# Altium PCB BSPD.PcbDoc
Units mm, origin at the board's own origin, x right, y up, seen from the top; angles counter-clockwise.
Board outline 53 x 50 mm, 2 copper layers (Top Layer, Bottom Layer), stack 1.57 mm thick; 78 components, 28 nets, 171 pads, 73 vias.
Unrouted connection lines stored in the file: 1.
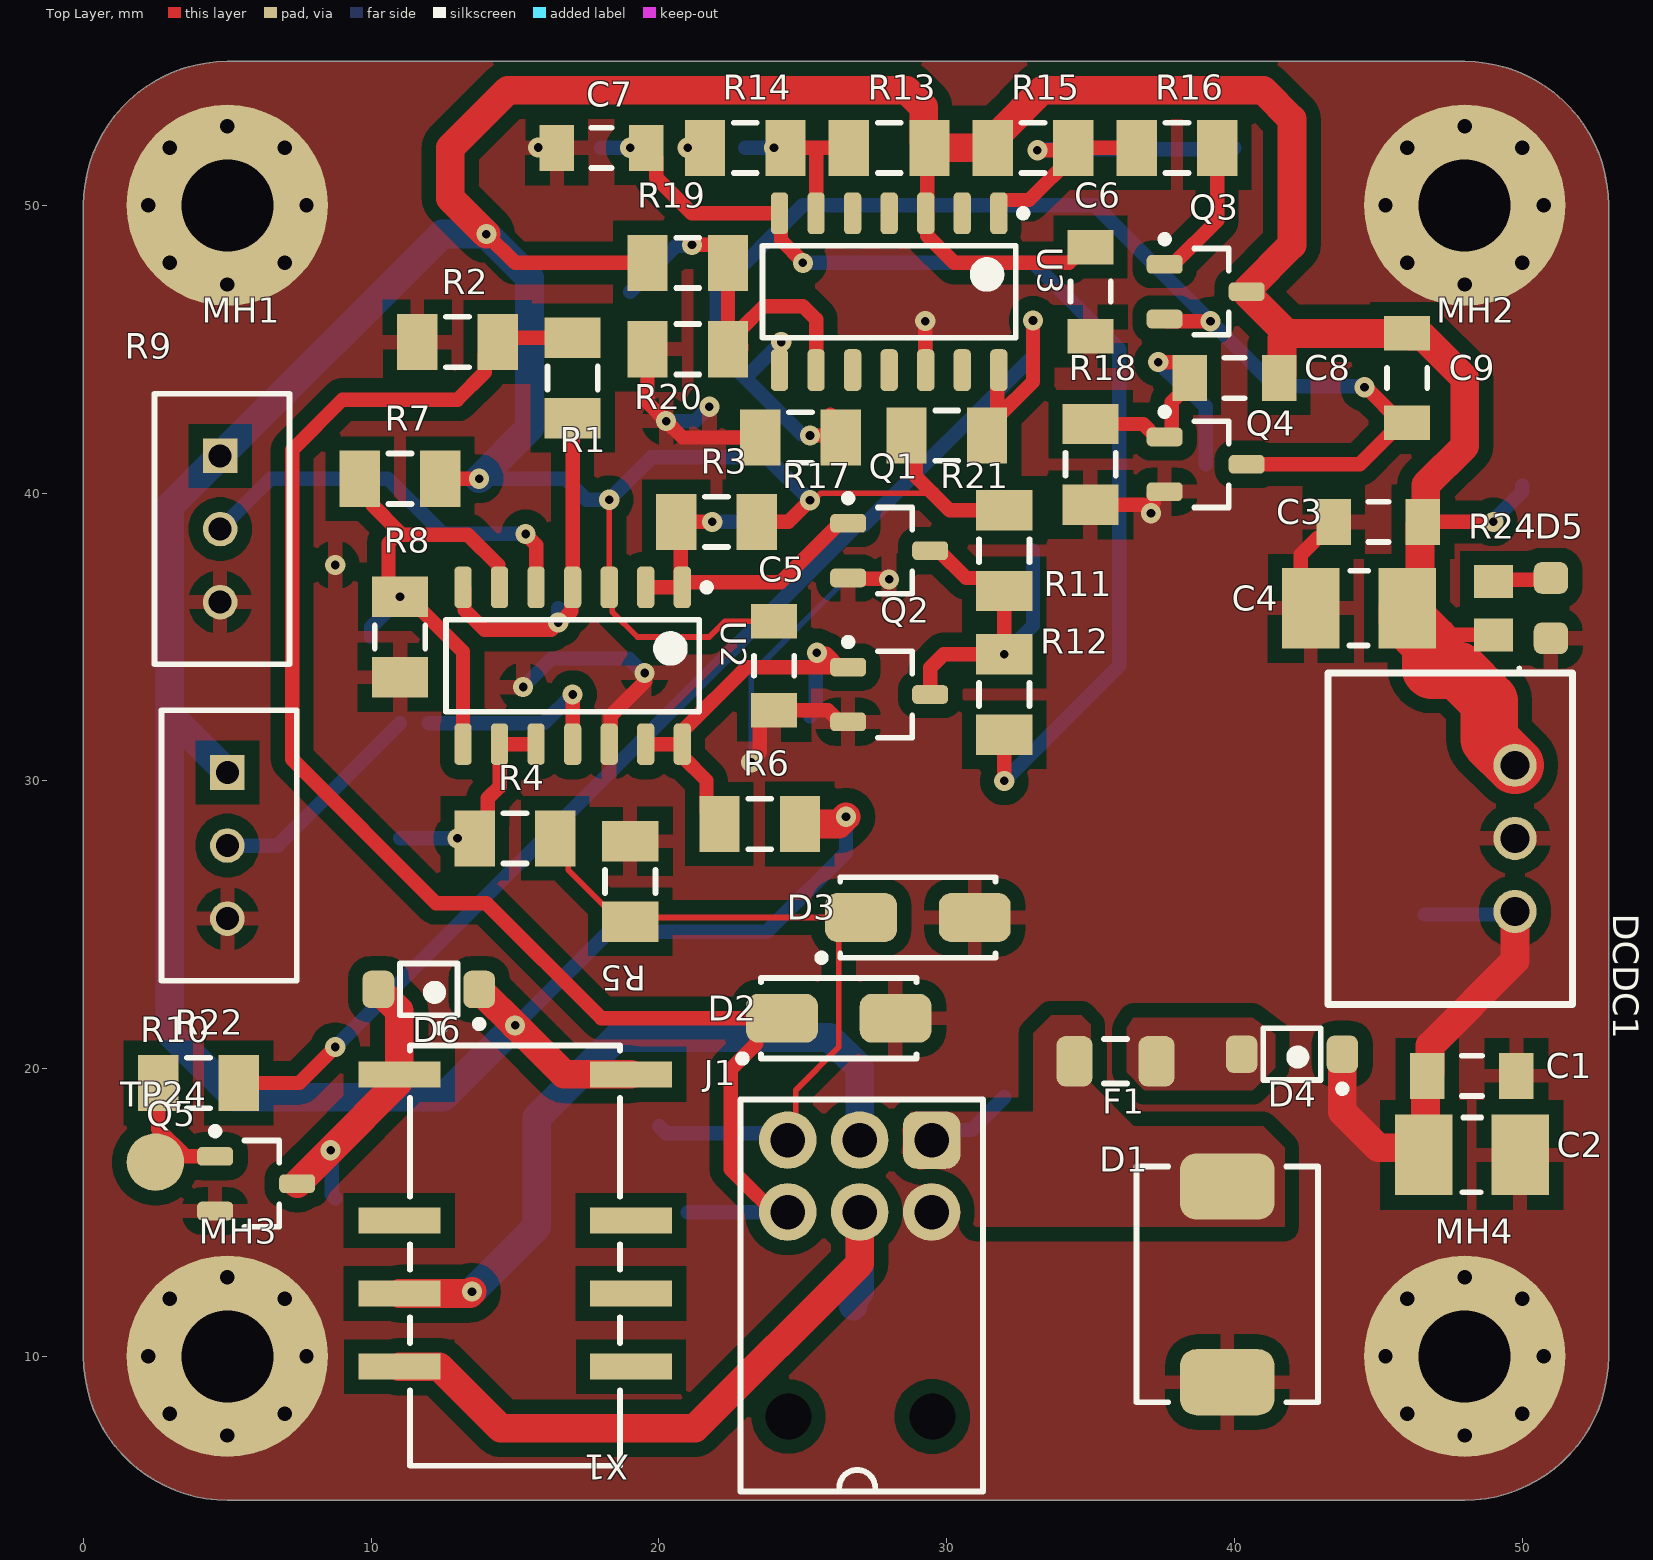
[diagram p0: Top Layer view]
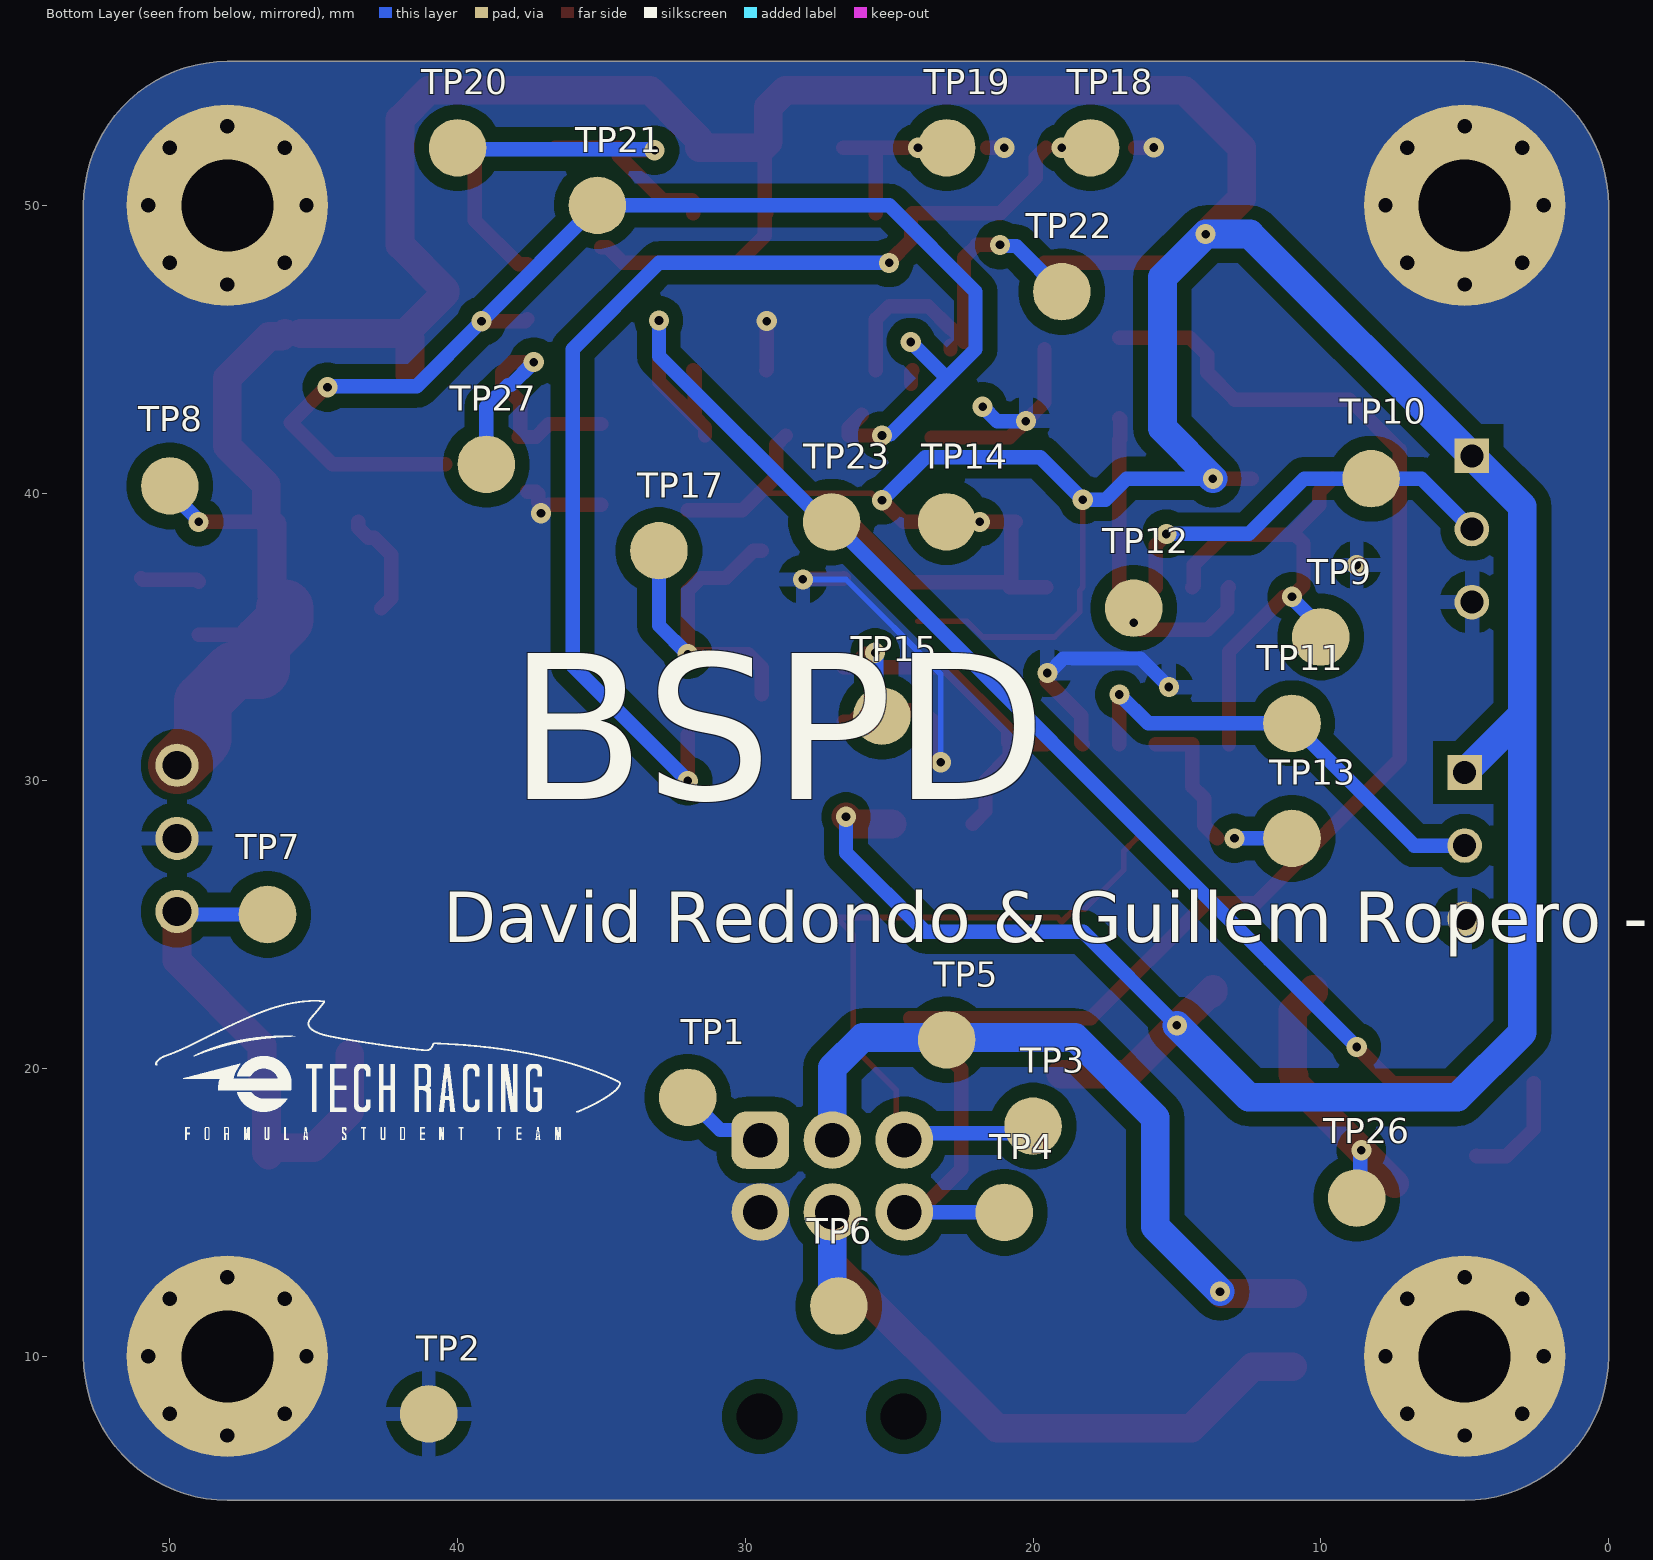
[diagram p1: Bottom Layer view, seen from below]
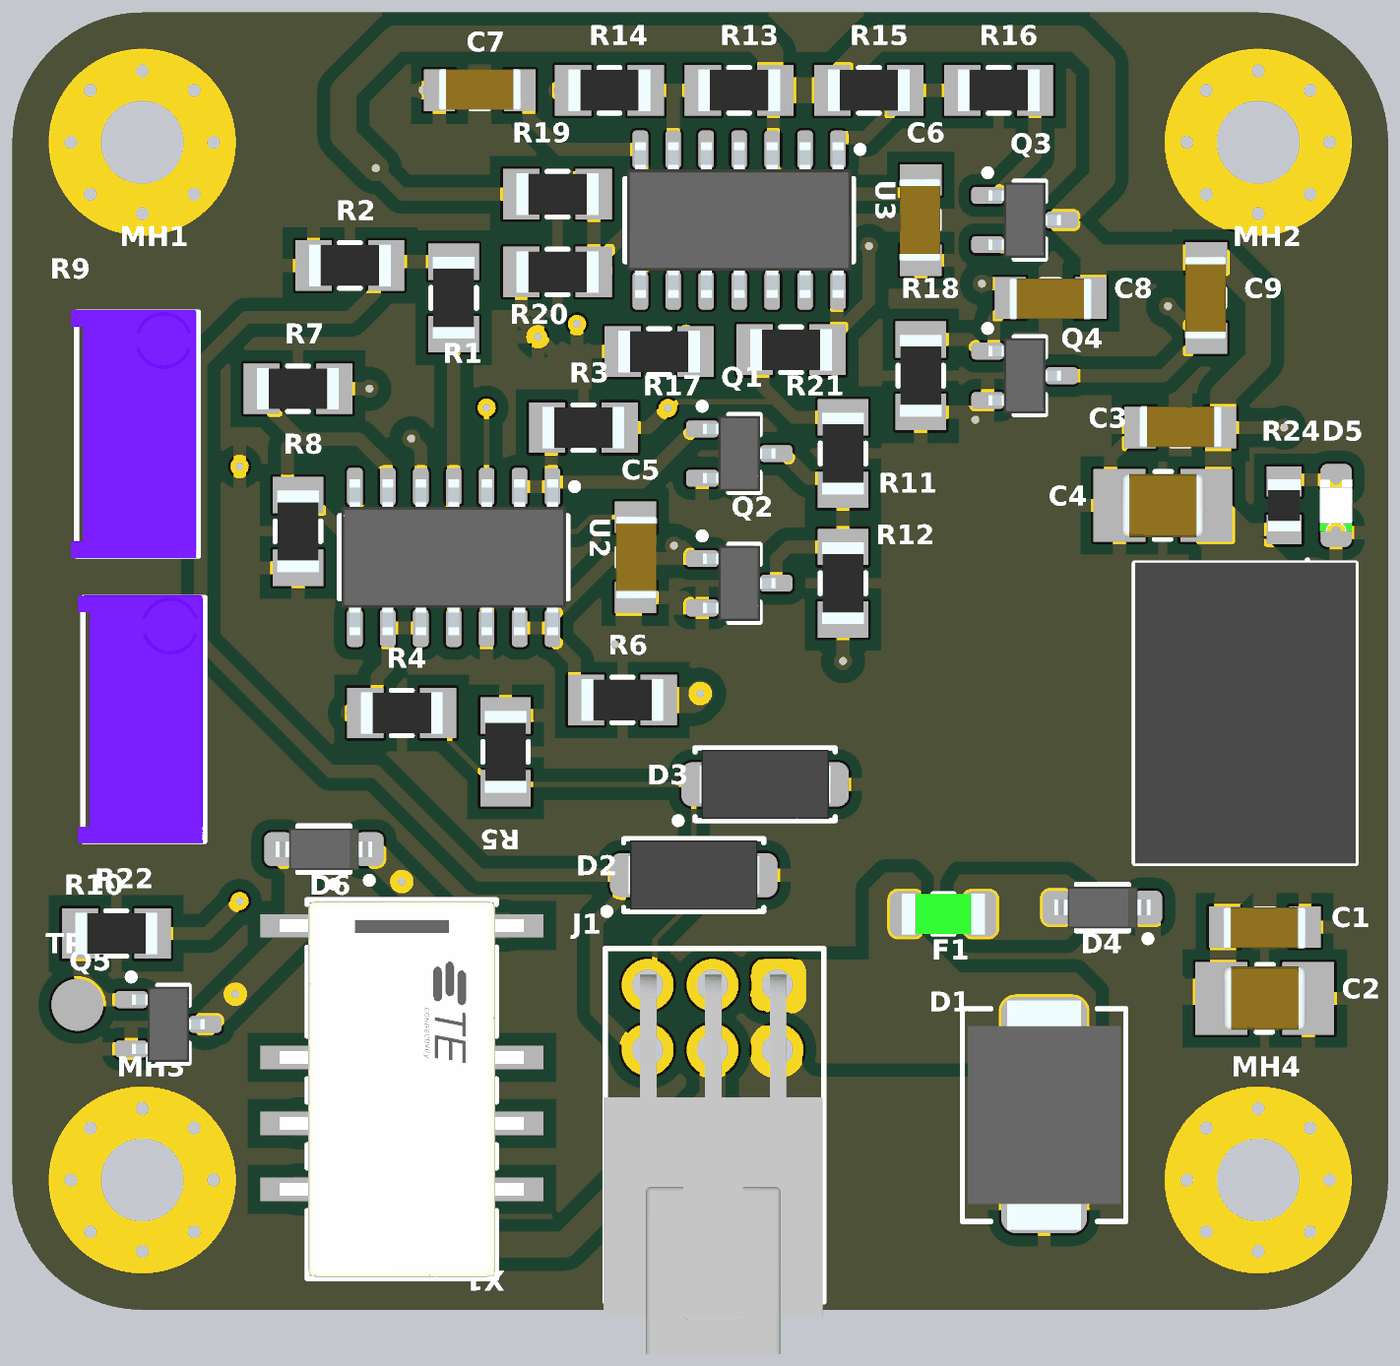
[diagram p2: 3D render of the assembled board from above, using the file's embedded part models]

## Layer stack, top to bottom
Top Solder: solder mask 0.01, Solder Resist, Dk 3.5
Top Layer: signal copper 0.035
Dielectric 1: dielectric 1.5, FR-4, Dk 4.8
Bottom Layer: signal copper 0.035
Bottom Solder: solder mask 0.01, Solder Resist, Dk 3.5

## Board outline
5,5 cw(c5,10) 0,10 0,50 cw(c5,50) 5,55 48,55 cw(c48,50) 53,50 53,10 cw(c48,10) 48,5

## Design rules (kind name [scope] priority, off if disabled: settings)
Clearance [All] p1: gap=0.5 ignorepadtopadclearanceinfootprint=FALSE
HoleSize [All] p1: absolutevalues=TRUE maxlimit=5 minlimit=0.025 maxpercent=80.000 minpercent=20.000
PolygonConnect [All] p1: connectstyle=Relief reliefconductorwidth=0.5 reliefentries=4 polygonreliefangle="90 Angle" airgapwidth=0.5
RoomDefinition BSPD [InComponentClass('BSPD')] p1: confinementstyle=ConfineIn formatcopy=TRUE lockcomponents=FALSE outline 0,66.75 65.75,66.75 65.75,1 0,1
RoutingVias [All] p1: holewidth=0.3 width=0.7 viastyle="Through Hole" minholewidth=0.2 minwidth=0.5 maxholewidth=3 maxwidth=5
SilkToSolderMaskClearance [IsPad] p1: minsilkscreentomaskgap=0 clearancetoexposedcopper=TRUE
SolderMaskExpansion [All] p1: expansion=0.102 istentingtop=FALSE
Width [All] p1: maxlimit=5 minlimit=0.2 preferedwidth=0.5
28 further rules are at their usual default settings.

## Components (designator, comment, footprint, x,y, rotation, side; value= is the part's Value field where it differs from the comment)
C1 "885012008055" C1206FNPC-RW 48.25,19.75 r180 top
C2 "GRJ32ER71H106KE11L" C10u-50V-1210FNPMLCC-X7R 48.25,17 r180 top
C3 "885012008055" C1206FNPC-RW 45,39 r0 top
C4 "GRJ32ER71H106KE11L" C10u-50V-1210FNPMLCC-X7R 44.325,36 r0 top
C5 "885012208058" C1206FNPC-RW 24,34 r270 top
C6 "885012208058" C1206FNPC-RW 35,47 r90 top
C7 "885012208018" C1206FNPC-RW 18,52 r0 top
C8 "885012208058" C1206FNPC-RW 40,44 r180 top
C9 "885012208036" C1206FNPC-RW 46,44 r90 top
D1 "824551301" DTVS-DO-214AB 39.75,12.5 r90 top
D2 "824501600" DTVS-DO-214AC 26.25,21.75 r180 top
D3 "824501600" DTVS-DO-214AC 29,25.25 r180 top
D4 "MBR0530" DSC-SOD123 42,20.5 r180 top
D5 "150080VS75000" LED_0805_WE 51,36 r90 top
D6 "MBR0530" DSC-SOD123 12,22.75 r180 top
DCDC1 "173951236" DCDC_Magi3c 49.75,28 r270 top
F1 "0437001.WRA" Fuse_1206 35.868,20.253 r0 top
J1 "J_NanoFit_2x3" J_NanoFit_2x3 27,11.5 r0 top
MH1 "Mounting_Hole_M3" Mounting_Hole_M3 5,50 r0 top
MH2 "Mounting_Hole_M3" Mounting_Hole_M3 48,50 r0 top
MH3 "Mounting_Hole_M3" Mounting_Hole_M3 5,10 r0 top
MH4 "Mounting_Hole_M3" Mounting_Hole_M3 48,10 r0 top
Q1 "CPH3455-TL-H" TRT-NCH-3/35-CPH 28,38 r0 top
Q2 "CPH3455-TL-H" TRT-NCH-3/35-CPH 28,33 r0 top
Q3 "CPH3455-TL-H" TRT-NCH-3/35-CPH 39,47 r0 top
Q4 "CPH3455-TL-H" TRT-NCH-3/35-CPH 39,41 r0 top
Q5 "CPH3455-TL-H" TRT-NCH-3/35-CPH 6,16 r0 top
R1 "CRCW120610K0FKEA" R1206FTK-W 17,44 r270 top
R2 "CRCW120610K0FKEA" R1206FTK-W 13,45.25 r0 top
R3 "CRCW120610K0FKEA" R1206FTK-W 22,39 r180 top
R4 "CRCW120610K0FKEA" R1206FTK-W 15,28 r180 top
R5 "CRCW120610K0FKEA" R1206FTK-W 19,26.5 r270 top
R6 "CRCW120610K0FKEA" R1206FTK-W 23.5,28.5 r180 top
R7 "CRCW120610K0FKEA" R1206FTK-W 11,40.5 r180 top
R8 "CR1206-FX-2201ELF" R1206FTK-W 11,35 r90 top
R9 "R10k-VTR" R10k-VTR 4.75,38.75 r0 top value=10k
R10 "R10k-VTR" R10k-VTR 5,27.75 r0 top value=10k
R11 "CRCW120610K0FKEA" R1206FTK-W 32,38 r270 top
R12 "CRCW120610K0FKEA" R1206FTK-W 32,33 r270 top
R13 "CRS1206-FX-4701ELF" R1206FTK-W 28,52 r0 top
R14 "CRCW120610K0FKEA" R1206FTK-W 23,52 r0 top
R15 "CRCW120610K0FKEA" R1206FTK-W 33,52 r0 top
R16 "CRG1206F100R" R1206FTK-W 38,52 r0 top
R17 "HVC1206-2M0FT3" R1206FTK-W 24.917,41.932 r0 top
R18 "CRCW120610K0FKEA" R1206FTK-W 35,41 r90 top
R19 "CRCW120610K0FKEA" R1206FTK-W 21,48 r180 top
R20 "CRCW120610K0FKEA" R1206FTK-W 21,45 r0 top
R21 "CRCW120610K0FKEA" R1206FTK-W 30,42 r0 top
R22 "CRG1206F100R" R1206FTK-W 4,19.5 r180 top
R24 "CR0805-JW-102ELF" R0805FTK 49,36 r270 top
TP1 "TestPoint" TestPoint 32,19 r180 bottom
TP2 "TestPoint" TestPoint 41,8 r180 bottom
TP3 "TestPoint" TestPoint 20,18 r180 bottom
TP4 "TestPoint" TestPoint 21,15 r180 bottom
TP5 "TestPoint" TestPoint 23,21 r180 bottom
TP6 "TestPoint" TestPoint 26.75,11.75 r90 bottom
TP7 "TestPoint" TestPoint 46.605,25.355 r180 bottom
TP8 "TestPoint" TestPoint 50,40.25 r180 bottom
TP9 "TestPoint" TestPoint 10,35 r180 bottom
TP10 "TestPoint" TestPoint 8.25,40.5 r90 bottom
TP11 "TestPoint" TestPoint 11,32 r90 bottom
TP12 "TestPoint" TestPoint 16.5,36 r90 bottom
TP13 "TestPoint" TestPoint 11,28 r90 bottom
TP14 "TestPoint" TestPoint 23,39 r90 bottom
TP15 "TestPoint" TestPoint 25.25,32.25 r90 bottom
TP17 "TestPoint" TestPoint 33,38 r90 bottom
TP18 "TestPoint" TestPoint 18,52 r90 bottom
TP19 "TestPoint" TestPoint 23,52 r90 bottom
TP20 "TestPoint" TestPoint 40,52 r90 bottom
TP21 "TestPoint" TestPoint 35.14,50 r90 bottom
TP22 "TestPoint" TestPoint 19,47 r90 bottom
TP23 "TestPoint" TestPoint 27,39 r90 bottom
TP24 "TestPoint" TestPoint 2.5,16.75 r90 top
TP26 "TestPoint" TestPoint 8.75,15.5 r90 bottom
TP27 "TestPoint" TestPoint 39,41 r0 bottom
U2 "LM339D" Array_4_Amp_LM339D 17,34 r270 top
U3 "LM339D" Array_4_Amp_LM339D 28,47 r270 top
X1 "Relay_SPDT_12V" FP-4-1393789-5-0 15,13.5 r270 top

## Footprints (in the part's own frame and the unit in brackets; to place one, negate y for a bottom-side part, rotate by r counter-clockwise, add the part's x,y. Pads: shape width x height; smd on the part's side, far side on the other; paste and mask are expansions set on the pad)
Array_4_Amp_LM339D [mm] "SOIC, 14-Leads, Body 8,65x3,90mm, Pitch 1,27mm, IPC Medium Density"
  rrect50% 1.45x0.6 smd: 1(-2.725,3.81) 2(-2.725,2.54) 3(-2.725,1.27) 4(-2.725,0) 5(-2.725,-1.27) 6(-2.725,-2.54) 7(-2.725,-3.81) 8(2.725,-3.81) 9(2.725,-2.54) 10(2.725,-1.27) 11(2.725,0) 12(2.725,1.27) 13(2.725,2.54) 14(2.725,3.81)
  silkscreen extent -2.85,-4.4 1.6,4.79, body extent -3,-4.33 3,4.33, height 1.75
C10u-50V-1210FNPMLCC-X7R [mm]
  rect 2x2.8 smd: 1(-1.675,0) 2(1.675,0)
  silkscreen extent -0.33,-1.3 0.33,1.3, body extent -1.6,-1.25 1.6,1.25, height 2.78
C1206FNPC-RW [mm] "Chip Capacitor, 2-Leads, Body 3,20x1,60mm, IPC Medium Density"
  rect 1.2x1.6 smd: 1(-1.55,0) 2(1.55,0)
  silkscreen extent -0.35,-0.7 0.35,0.7, body extent -1.59,-0.77 1.61,0.83, height 0.91
DCDC_Magi3c [mm]
  round 1.5 hole 1: 1(2.54,0) 2(0,0) 3(-2.54,0)
  silkscreen extent -5.75,-6.5 5.77,2, body extent -5.8,-6.5 5.8,2, height 10.2
DSC-SOD123 [mm] "SOIC, 2-Leads, Body 1,60x2,69mm, Pitch 1,27mm, IPC Low Density"
  rrect50% 1.1x1.3 smd: A(1.75,0) K(-1.75,0)
  silkscreen extent -1.88,-0.9 1,1.32, body extent -1.86,-0.8 1.86,0.8, height 1.36
DTVS-DO-214AB [mm] "Molded Diode, 2-Leads, Body 7,94x5,90mm"
  rrect50% 2.3x3.3 smd: 1(-3.4,0) 2(3.4,0)
  silkscreen extent -4.1,-3.15 4.1,3.15, body extent -4.42,-2.95 4.42,2.95, height 2.9
DTVS-DO-214AC [mm] "Molded Diode, 2-Leads, Body 5,11x2,67mm, IPC Medium Density"
  rrect50% 2.5x1.7 smd: 1(-1.975,0) 2(1.975,0)
  silkscreen extent -2.7,-1.4 3.47,1.52, body extent -2.56,-1.34 2.56,1.34, height 2.5
FP-4-1393789-5-0 [mm]
  rect 0.9x2.85 smd paste+0 mask+0: 1(-6.3,-4.025) 3(-1.22,-4.025) 4(1.32,-4.025) 5(3.86,-4.025) 8(3.86,4.025) 9(1.32,4.025) 10(-1.22,4.025) 12(-6.3,4.025)
  silkscreen extent -8.02,-3.65 7.3,3.65, body extent -7.4,-5.55 7.4,5.55, height 0.25
Fuse_1206 [mm] "Chip Resistor, 2-Leads, Body 3,20x1,58mm, IPC Medium Density"
  rrect50% 1.25x1.75 smd: 1(-1.425,0) 2(1.425,0)
  silkscreen extent -0.4,-0.77 0.4,0.77, body extent -1.6,-0.79 1.6,0.79, height 0.86
J_NanoFit_2x3 [mm]
  rrect50% 2x2 hole 1.2: 1(2.475,6.015)
  round 2 hole 1.2: 2(-0.025,6.015) 3(-2.525,6.015) 4(2.475,3.515) 5(-0.025,3.515) 6(-2.525,3.515)
  round 1.524 hole 1.6: ""(-2.5,-3.59) ""(2.5,-3.59)
  silkscreen extent -4.18,-6.2 4.26,7.42, body extent -4.22,-8.23 4.22,6.43, height 9.35
LED_0805_WE [mm] "SODFL, 2-Leads, Body 1,60x3,20mm, IPC Medium Density"
  rrect50% 1.1x1.2 smd: A(1.05,0) K(-1.05,0)
  silkscreen extent -2.15,1.05 -2.05,1.15, body extent -1,-0.62 1,0.63, height 0.7
Mounting_Hole_M3 [mm]
  round 7 hole 3.2: 1(0,0)
R10k-VTR [mm]
  rect 1.2x1.2 hole 0.8: 1(0,2.54)
  round 1.2 hole 0.8: 2(0,-2.54) 3(0,0)
  silkscreen extent -2.29,-4.7 2.41,4.7, body extent -2.49,-4.78 2.34,4.78, height 11.09
R0805FTK [mm] "Chip Resistor, 2-Leads, Body 2,00x1,25mm, IPC Medium Density"
  rect 1.15x1.35 smd: 1(-0.925,0) 2(0.925,0)
  body extent -1,-0.63 1,0.63, height 0.65
R1206FTK-W [mm] "Chip Resistor, 2-Leads, Body 3,15x1,60mm, IPC Medium Density"
  rect 1.4x1.95 smd: 1(-1.4,0) 2(1.4,0)
  silkscreen extent -0.4,-0.87 0.4,0.87, body extent -1.58,-0.8 1.58,0.8, height 0.61
TestPoint [mm]
  round 2 smd: 1(0,0)
TRT-NCH-3/35-CPH [mm] "SOT23, 3-Leads, Body 2,90x2,80mm, Pitch 0,95mm, IPC Low Density"
  rrect50% 1.25x0.65 smd: D(1.425,0) G(-1.425,0.95) S(-1.425,-0.95)
  silkscreen extent -1.55,-1.5 0.8,1.95, body extent -1.4,-1.45 1.4,1.45, height 1.06

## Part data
C1 C3: library part C10n-50V-1206FNPC-C0G/NP0, "Cap Cer 10000PF 50V C0G/NP0 1206", Capacitance=10nF, Case Code (Imperial)=1206, Case Code (Metric)=3216, Manufacturer="Wurth Electronics", Max Operating Temperature=125°C, Min Operating Temperature=-55°C, Supplier Part Number 1=710-885012008055, Tolerance=5%, Voltage Rating=50V
C2 C4: library part C10u-50V-1210FNPMLCC-X7R, "Multilayer Ceramic Capacitors MLCC - SMD/SMT 1210 10uF 50volts X7R +/-10% Soft Term", Capacitance=10uF, Case Code (Imperial)=1210, Case Code (Metric)=3225, Manufacturer=Murata, Max Operating Temperature=125°C, Min Operating Temperature=-55°C, Tolerance=10%, Voltage Rating=50V
C5 C6 C8: library part C100n-25V-1206FNPC-X7R, "Cap Cer 0.1UF 25V X7R 1206", Capacitance=100nF, Case Code (Imperial)=1206, Case Code (Metric)=3216, Manufacturer="Wurth Electronics", Max Operating Temperature=125°C, Min Operating Temperature=-55°C, Supplier Part Number 1=732-8109-1-ND, Tolerance=10%, Voltage Rating=25V
C7: library part C10u-10V-1206FNPC-X7R, "Cap, 10ΜF, 10V, 10%, X7R, 1206", Capacitance=10uF, Case Code (Imperial)=1206, Case Code (Metric)=3216, Manufacturer 1="Wurth Electronics", Max Operating Temperature=125°C, Min Operating Temperature=-55°C, Supplier Part Number 1=732-7565-1-ND, Tolerance=10%, Voltage Rating=10V
C9: library part C1u-16V-1206FNPC-X7R, "Cap Cer 1UF 16V X7R 1206", Capacitance=1uF, Case Code (Imperial)=1206, Case Code (Metric)=3216, Manufacturer="Wurth Electronics", Max Operating Temperature=125°C, Min Operating Temperature=-55°C, Supplier Part Number 1=710-885012208036, Tolerance=10%, Voltage Rating=16V
D1: library part DTVS-40V-DO-214AB, "TVS diode [Würth Elektronik] 824551301 TVS diode", Clamping Voltage=48.4V, Manufacturer="Wurth Electronics", Max Breakdown Voltage=35.05V, Max Operating Temperature=150°C, Min Operating Temperature=-65°C, Peak Pulse Current=62A, Peak Pulse Power=3kW, Power Line Protection=No, Resistor Type=Zener, Reverse Standoff Voltage=30V, Supplier Part Number 1=9217092P
D2 D3: library part DTVS-6V-DO-214AC, "TVS diode [Würth Elektronik] 824501600 TVS diode", Clamping Voltage=10.3V, Manufacturer="Wurth Electronics", Max Breakdown Voltage=7.02V, Max Operating Temperature=150°C, Min Operating Temperature=-65°C, Peak Pulse Current=38.8A, Peak Pulse Power=400W, Power Line Protection=No, Resistor Type=Zener, Reverse Standoff Voltage=6V, Supplier Part Number 1=710-824501600
D4 D6: library part DSC-0.5/30-SOD123, "VR=30V IF=500mA 30pF P=410mW", Average Rectified Current=500mA, Forward Voltage=430mV, Max Forward Surge Current (Ifsm)=5.5A, Max Repetitive Reverse Voltage (Vrrm)=30V, Max Reverse Current=130uA, Package Quantity=1, Supplier Part Number 1=15R3453
D5: library part LEDVS-0805-40, "Led, Green, 570 Nm, 2 V, 30 Ma, 40 Mcd Rohs Compliant: Yes", Case Code (Imperial)=0805, Case Code (Metric)=2012, Color=Green, Forward Current=30mA, Forward Voltage=2V, Manufacturer 1="Wurth Electronics", Max Operating Temperature=85°C, Min Operating Temperature=-40°C, Package Quantity=4000, Supplier Part Number 1=8154237, Test Current=20mA
DCDC1: library part DCDC-36V/12V-0.5A, "Fdsm Fixed Step Down Regulator M", Manufacturer 1="Wurth Electronics", Supplier Part Number 1=732-173951236-ND
F1: library part Fuse_1A_63V_1206, "Fuse Chip Fast Acting 1A 63V SMD Solder Pad 1206 Ceramic T/R Automotive", Case Code (Imperial)=1206, Case Code (Metric)=3216, Current Rating=1A, Manufacturer=Littelfuse, Max Operating Temperature=150°C, Min Operating Temperature=-55°C, Supplier Part Number 1=F10001CT-ND, Voltage Rating (AC)=63V
Q1 Q2 Q3 Q4 Q5: library part TRT-NCH-3/35-CPH, "CPH3455-TL-H N-channel MOSFET Transistor; 3 A; 35 V; 3-Pin CPH", Case/Package=SC, Continuous Drain Current (ID)=3A, Drain to Source Breakdown Voltage=35V, Drain to Source Resistance=108mR, Gate to Source Voltage (Vgs)=20V, Input Capacitance=186pF, Manufacturer="ON Semiconductor", Max Operating Temperature=150°C, Max Power Dissipation=1W, Min Operating Temperature=-55°C, Package Quantity=3000, Supplier Part Number 1=8009989
R1 R3 R4 R6 R11 R14 R15 R19 R20 R21: library part R10k-1206FTK, "Res Thick Film 1206 10K Ohm 1% 0.25W(1/4W) +/-100ppm/ßC Pad SMD Automotive T/R", Case Code (Imperial)=1206, Case Code (Metric)=3216, Package Quantity=10, Package Shape=Rectangular, Resistance=10kR, Resistance Tolerance=1%, Resistor Type="Thick Film", Supplier Part Number 1=70201262, Temperature Coefficient=100ppm/°C, Voltage Rating=200V
R2 R5 R7 R12 R18: library part R51k-1206FTK, "Res Thick Film 1206 51K Ohm 1% 1/4W ±100ppm/°C Molded SMD SMD Punched Carrier T/R", Case Code (Imperial)=1206, Case Code (Metric)=3216, Current Rating=2A, Manufacturer=Panasonic, Manufacturer Part Number=ERJ-S08F5102V, Max Operating Temperature=155°C, Max Power Dissipation=250mW, Min Operating Temperature=-55°C, Package Quantity=5000, Resistance=51kR, Resistor Type="Thick Film", Supplier Part Number 1=667-ERJ-S08F5102V, Temperature Coefficient=100ppm/°C, Tolerance=1%, Voltage Rating=150V, Voltage Rating (DC)=200V
R8: library part R2.2K-1206FTK, "Res Thick Film 1206 2.2K Ohm 1% 1/4W ±100ppm/°C Molded SMD SMD Paper Tape on Plastic Reel", Case Code (Imperial)=1206, Case Code (Metric)=3216, Manufacturer 1=Bourns, Max Operating Temperature=155°C, Max Power Dissipation=250mW, Min Operating Temperature=-55°C, Package Quantity=5000, Resistance=2.2kR, Resistance Tolerance=1%, Resistor Type="Thick Film", Supplier Part Number 1=CR1206-FX-2201ELFCT-ND, Temperature Coefficient=100ppm/°C, Voltage Rating=200V
R9 R10: library part CMP-00072-1, "Trimmer, Cermet, Rest 10 Kilohms, PCB, 25 Turns, Pwr-Rtg 0.5W, 3296 Series", Color=Blue, Insulation Resistance=1GR, Manufacturer=Bourns, Manufacturer Part Number=3296W-1-103LF, Max Operating Temperature=125°C, Max Power Dissipation=500mW, Min Operating Temperature=-55°C, Package Quantity=50, Resistance Tolerance=10%, Resistor Type=Cermet, Temperature Coefficient=100ppm/°C
R13: library part R4.7K-1206FTK, "Res Thick Film 1206 4.7K Ohm 1% 1/2W ±100ppm/°C Molded SMD T/R", Case Code (Imperial)=1206, Case Code (Metric)=3016, Manufacturer 1="Bourns JW Miller", Max Operating Temperature=155°C, Max Power Dissipation=500mW, Min Operating Temperature=-55°C, Resistance=4.7kR, Resistor Type="Thick Film", Supplier Part Number 1=CRS1206-FX-4701ELFCT-ND, Temperature Coefficient=100ppm/°C, Tolerance=1%, Voltage Rating=400V
R16 R22: library part R100-1206FTK, "Res Thick Film 1206 100 Ohm 1% 0.25W(1/4W) ±200ppm/C Pad SMD T/R", Case Code (Imperial)=1206, Case Code (Metric)=3216, Manufacturer="TE Connectivity", Max Operating Temperature=125°C, Max Power Dissipation=250mW, Min Operating Temperature=-55°C, Number of Resistors=1, Package Quantity=5000, Resistance=100R, Resistor Type="Thick Film", Supplier Part Number 1=A106068CT-ND, Temperature Coefficient=200ppm/°C, Tolerance=1%, Voltage Rating=200V
R17: library part R2M-1206FTK, "Res Thick Film 1206 2M Ohm 1% 0.3W ±100ppm/C Pad SMD T/R", Case Code (Imperial)=1206, Case Code (Metric)=3216, Manufacturer="TT Welwyn", Power rating=300mW, Resistance=2MR, Resistor Type="Thick Film", Supplier Part Number 1=6119491, Temperature Coefficient=100ppm/°C, Tolerance=1%, Voltage Rating=1kV
R24: library part R1k-0805FTK, "Res Thick Film 0805 1K Ohm 5% 1/8W ±200ppm/°C Molded SMD SMD Paper Tape on Plastic Reel", Case Code (Imperial)=0805, Case Code (Metric)=2012, Manufacturer 1=Bourns, Max Operating Temperature=155°C, Max Power Dissipation=125mW, Min Operating Temperature=-55°C, Package Quantity=1, Resistance=1kR, Resistor Type="Thick Film", Temperature Coefficient=200ppm/°C, Tolerance=5%, Voltage Rating=150V
TP1 TP2 TP3 TP4 TP5 TP6 TP7 TP8 TP9 TP10 TP11 TP12 TP13 TP14 TP15 TP17 TP18 TP19 TP20 TP21 TP22 TP23 TP24 TP26 TP27: "Test Point 1x1 mm"
U2 U3: library part Array_4_Comp_LM339D, "Comparator Quad ±18V/36V 14-Pin SOIC Tube", Case/Package=SOIC, Dual Supply Voltage=9V, Input Bias Current=250nA, Input Offset Voltage (Vos)=5mV, Manufacturer="Texas Instruments", Max Dual Supply Voltage=15V, Max Operating Temperature=70°C, Max Supply Current=500uA, Max Supply Voltage=30V, Min Dual Supply Voltage=1V, Min Operating Temperature=0°C, Min Supply Voltage=2V, Nominal Supply Current=2mA, Output Current=20mA, Output Current per Channel=6mA, Package Quantity=50, Quiescent Current=2.5mA, Supplier Part Number 1=296-1013-5-ND, Voltage Gain=106.02dB
X1: library part CMP-00219-1, "RF Relay, 2 Form C, DPDT, Momentary, 0.012A (Coil), 12VDC (Coil), 140mW (Coil), 5A (Contact), 220VDC (Contact), 900MHz, 60W (RF Input), DC Input, Random, AC/DC Output, Surface Mount-Straight", Coil Current(DC)-Max=12mA, Coil Operate Voltage(DC)=26.15V, Coil Power=140mW, Coil Release Voltage(DC)=1.2V, Coil Resistance=1.029kR, Coil Voltage(DC)-Max=12V, Contact AC Max Power Rating R Load=62.5VA@250VAC, Contact AC Max Rating R Load=5A@250VAC, Contact Current(AC)-Max=5A, Contact DC Max Power Rating R Load=60W@220VDC, Contact DC Max Rating R Load=5A@220VDC, Contact Resistance=50mR, Contact Voltage(AC)-Max=250V, Contact Voltage(DC)-Max=220V, Dielectric Strength Between Coil and Contacts=1500Vrms, Dielectric Strength Between Open Contacts=1000Vrms, Input Power-Max=60W, Insulation Resistance=1GR, Manufacturer Series=1393789, Max Operating Temperature=85°C, Min Operating Temperature=-40°C, Operating Frequency-Max=900MHz, Operating Frequency-Min=100MHz

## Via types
v1: diameter 0.7, hole 0.5, Top Layer to Bottom Layer, tented both sides, 32 vias
v2: diameter 0.7, hole 0.3, Top Layer to Bottom Layer, tented both sides, 29 vias
v3: diameter 0.7, hole 0.3, Top Layer to Bottom Layer, 12 vias

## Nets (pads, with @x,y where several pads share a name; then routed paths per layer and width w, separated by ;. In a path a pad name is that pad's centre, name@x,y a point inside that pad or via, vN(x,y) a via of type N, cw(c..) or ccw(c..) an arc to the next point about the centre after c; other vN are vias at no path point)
+12: C3.2 C4.2 C5.1 C6.2 C8.1 C9.2 D6.K DCDC1.3 Q3.D R3.1 R6.1 R7.1 R9.1 R10.1 R11.1 R13.2 R15.1 R19.2 R21.1 R24.2 TP8.1 U2.3 U3.3 X1.12 | length 214.1
  Top Layer w0.2: v3(18.27,39.77) U2.3 18.378,36.617 18.378,35.872 19.25,35 21.75,35 22.3,35.55 C5.1 ; v3(25.25,39.75) 25.376,39.75 25.617,39.991 29.509,39.991
  Top Layer w0.5: R7.1 v2(13.75,40.5) ; v2(14,49) 15,48 R19.2 ; R3.1 24.5,39 25,39.5 v3(25.25,39.75) ; R21.1 28.918,41.682 28.918,40.582 29.509,39.991 30.1,39.4 R11.1 ; R13.2@29.32,52.08 29.32,49.775 U3.3 29.32,49.675 29.32,48.947 30.267,48 34.25,48 34.8,48.55 C6.2 ; 43.389,45.389 45.839,45.389 C9.2 ; C4.2@46,35.075 R24.2 ; C3.2@46.45,38.9 C3.2 v2(49,39)
  Top Layer w1: D6.K 13.75,22.65 13.8,22.6 13.9,22.6 v3(15,21.5) 16.7,19.8 X1.12 ; v2(14,49) 12.75,50.25 12.75,52 14.75,54 28.614,54 29.2,53.414 R13.2@29.2,52.2 ; R6.1 26.25,28.5 v3(26.5,28.75) ; R13.2 R15.1 31.6,52.275 32.579,53.254 32.579,53.268 33.311,54 41,54 42,53 42,48.625 40.425,47.05 Q3.D 40.425,46.95 41.825,45.55 ; C8.1 41.65,44.1 41.65,45.375 41.825,45.55 ; C9.2@45.45,45.55 41.825,45.55 ; C4.2 46.45,36.45 C3.2@46.45,38.9 ; C9.2 46.1,45.45 46.55,45.45 48,44 48,41.636 46.65,40.286 46.65,39.1 C3.2
  Top Layer w2: C4.2 46,35.6 46.825,34.775 46.825,33.879 46.854,33.85 47.766,33.85 48.85,32.766 48.85,31.44 DCDC1.3
  Bottom Layer w0.5: v2(13.75,40.5) 16.75,40.5 17.48,39.77 v3(18.27,39.77) 19.75,41.25 23.75,41.25 v3(25.25,39.75) ; v3(15,21.5) 18.25,24.75 23.75,24.75 26.5,27.5 v3(26.5,28.75) ; v2(49,39) 49,39.054 50,40.054 TP8.1
  Bottom Layer w1: R10.1 3,32.29 ; v2(13.75,40.5) 15.5,42.25 15.5,47.5 v2(14,49) 12.46,49 R9.1 3,39.54 3,32.29 ; v3(15,21.5) 12.5,19 5.25,19 3,21.25 3,32.29
Brake_in: D3.2 J1.3 R4.1 R5.2 TP3.1 | length 25.7
  Top Layer w0.2: R4.1 16.85,27.55 16.85,26.9 18.2,25.55 18.55,25.55 R5.2 19.15,25.25 D3.2@26.837,25.25 ; J1.3 24.75,17.79 24.75,19.25 26.25,20.75 26.25,24.663 D3.2@26.837,25.25 ; D3.2 D3.2@26.837,25.25
  Bottom Layer w0.5: TP3.1 20.242,17.757 24.232,17.757 J1.3
Brake_trig_lvl: R10.3 TP11.1 U2.11 | length 14.9
  Top Layer w0.5: U2.11 v2(17,33)
  Bottom Layer w0.5: R10.3 6.75,27.75 TP11.1 ; 12,32 16,32 v2(17,33)
Brake_trigger: Q2.G R6.2 TP15.1 U2.13 U2.14 | length 15
  Top Layer w0.5: U2.13 U2.14 ; R6.2 21.65,28.95 21.65,30.01 20.81,30.85 U2.14 ; v2(25.487,34.45) 25.526,34.412 25.813,34.412 Q2.G@26.275,33.95 ; Q2.G Q2.G@26.275,33.95 ; U2.14 20.86,31.325 20.86,31.771 23.039,33.95 Q2.G@26.275,33.95
  Bottom Layer w0.5: TP15.1 25.449,32.449 25.449,34.412 v2(25.487,34.45)
GND: C1.1 C2.1 C3.1 C4.1 C5.2 C6.1 C7.1 D1.1 D2.1 D3.1 D5.K DCDC1.2 J1.4 MH1.1 MH2.1 MH3.1 MH4.1 Q1.S Q2.S Q4.S Q5.S R2.1 R5.1 R8.1 R9.2 R10.2 R14.1 R17.1 R18.1 R20.1 TP2.1 U2.12 U3.12 | length 40.8
  Top Layer w0.5: v2(15.802,52.009) 15.811,52 C7.1 ; U2.12 18.32,31.325 18.32,32.266 v3@19.519,33.465 ; R20.1 19.6,43.15 v3(20.25,42.5) 20.818,41.932 R17.1 ; v2(21,52) R14.1 ; v2(23.207,30.646) 23.207,30.7 23.5,30.992 23.5,32.1 23.85,32.45 C5.2 25.875,32.45 26.275,32.05 Q2.S ; Q1.S 26.6,37.025 27.975,37.025 v2(28,37) ; v2(29.257,45.978) 29.257,44.288 U3.12 ; R18.1 36.825,39.6 ; v2(37.1,39.302) 37.138,39.34 37.138,39.613 37.2,39.675 37.2,39.975 37.275,40.05 Q4.S ; C4.1 42.307,36.343 42.307,37.857 42.9,38.45 43.1,38.45 43.45,38.8 C3.1
  Bottom Layer w0.2: v2(23.207,30.646) 23.207,33.707 26.5,37 v2(28,37)
  Bottom Layer w0.5: v3(15.277,33.26) 16.268,34.25 18.946,34.25 19.446,33.75 v3(19.5,33.75) ; v3(20.25,42.5) 21.25,42.5 v3(21.75,43)
  other v1: 5,7.25 48,7.25 3,8 7,8 46,8 50,8 2.25,10 7.75,10 45.25,10 50.75,10 3,12 7,12 46,12 50,12 5,12.75 48,12.75 5,47.25 48,47.25 3,48 7,48 46,48 50,48 2.25,50 7.75,50 45.25,50 50.75,50 3,52 7,52 46,52 50,52 5,52.75 48,52.75
  other v3: 8.75,37.5
Hall_in: D2.2 J1.6 R1.1 R2.2 TP4.1 | length 55.7
  Top Layer w0.5: R1.1 14.55,45.4 R2.2 13.95,44.8 13.95,44.2 13,43.25 9,43.25 7.25,41.5 7.25,30.75 12.25,25.75 14,25.75 18,21.75 D2.2@23.97,21.75 ; D2.2 D2.2@23.97,21.75 ; J1.6 24.475,14.605 24.395,14.605 22.5,16.5 22.5,19.975 23.383,20.858 23.383,21.163 D2.2@23.97,21.75
  Bottom Layer w0.5: TP4.1 21.007,15.007 24.467,15.007 J1.6
Hall_trig_lvl: R9.3 TP10.1 U2.5 | length 14.1
  Top Layer w0.5: v2(15.365,38.581) 15.365,38.561 15.73,38.196 U2.5
  Bottom Layer w0.5: R9.3 6.5,40.5 10.58,40.5 12.499,38.581 v2(15.365,38.581)
Hall_trigger: Q1.G R3.2 TP14.1 U2.1 U2.2 | length 12.7
  Top Layer w0.5: U2.2 U2.1 20.76,36.775 20.76,38.84 R3.2 v2(21.85,39) ; U2.1@20.81,36.85 20.86,36.9 24.225,36.9 26.275,38.95 Q1.G
  Bottom Layer w0.5: v2(21.85,39) TP14.1
Halt: R15.2 R16.1 TP20.1 U3.1 | length 14.3
  Top Layer w0.5: U3.1 31.81,50.135 31.86,50.185 32.86,50.185 34.4,51.725 R15.2 ; v2(33.15,51.916) 34.316,51.916 R15.2 ; R16.1 R15.2
  Bottom Layer w0.5: v2(33.15,51.916) 33.188,51.954 39.954,51.954 TP20.1
Implausability: C7.2 R12.2 TP18.1 U3.7 | length 39.5
  Top Layer w0.5: C7.2 19.9,51.65 19.9,50.964 21.139,49.725 U3.7 24.24,49.675 24.24,48.796 25,48.036 v2(25,48) ; v2(32,30) R12.2
  Bottom Layer w0.5: TP18.1 v2(19,52) ; v2(25,48) 33,48 36,45 36,34 v2(32,30)
LV+_in: D1.2 F1.1 J1.1 TP1.1 | length 3.1
  Bottom Layer w0.5: J1.1 29.825,17.865 30.865,17.865 TP1.1
NetC1_2: C1.2 C2.2 D4.K DCDC1.1 TP7.1 | length 18.4
  Top Layer w1: D4.K 43.75,18.5 45,17.25 46.325,17.25 C2.2 46.637,17.062 46.637,19.687 C1.2 46.8,19.85 46.8,20.8 49.75,23.75 DCDC1.1
  Bottom Layer w0.5: TP7.1 49.645,25.355 DCDC1.1
NetC8_2: C8.2 Q4.G R18.2 TP27.1 | length 11.1
  Top Layer w0.5: R18.2 36.825,42.4 37.275,41.95 37.875,41.95 37.817,42.008 37.817,43.167 38.45,43.8 38.45,44.2 38.1,44.55 37.352,44.55 v2(37.35,44.552)
  Bottom Layer w0.5: v2(37.35,44.552) 38.145,43.757 38.243,43.757 39,43 TP27.1
NetD4_A: D4.A F1.2
NetD5_A: D5.A R24.1 | length 2.1
  Top Layer w0.5: R24.1 49.062,36.987 50.937,36.987 D5.A
NetD6_A: D6.A Q5.D TP26.1 X1.1 | length 10.3
  Top Layer w1: Q5.D v3(8.587,17.163) 10.925,19.5 10.925,19.75 X1.1 10.975,22.014 10.389,22.6 10.3,22.6 10.25,22.65 D6.A
  Bottom Layer w0.5: v3(8.587,17.163) 8.626,17.124 8.626,15.624 TP26.1
NetQ1_D: Q1.D Q2.D R11.2 R12.1 TP17.1 | length 13.1
  Top Layer w0.5: Q2.D 29.425,33.925 29.9,34.4 v2(32,34.4) R11.2 31.55,37.05 30.675,37.05 29.725,38 Q1.D
  Bottom Layer w0.5: v2(32,34.4) 33,35.4 TP17.1
NetQ3_G: Q3.G R16.2 | length 5
  Top Layer w0.5: Q3.G 37.875,47.95 39.4,49.475 R16.2
NetQ5_G: Q5.G R22.2 TP24.1 | length 4
  Top Layer w0.5: R22.2 2.6,17.9 3.55,16.95 Q5.G Q5.G@4.6,16.975
NetR1_2: R1.2 TP12.1 U2.4 U2.7 | length 12.3
  Top Layer w0.5: U2.7 13.24,36.675 13.24,35.947 13.937,35.25 16.253,35.25 v2@16.501,35.499 ; v2(16.5,35.5) 16.538,35.538 16.595,35.538 16.95,35.893 16.95,36.675 U2.4 17,41.857 16.975,41.882 16.975,42.575 R1.2
  Bottom Layer w0.5: v2(16.5,35.5) TP12.1
NetR4_2: R4.2 TP13.1 U2.9 U2.10 | length 6.9
  Top Layer w0.5: R4.2 14.05,28.45 14.05,29.39 14.46,29.8 U2.9 U2.10
  Bottom Layer w0.5: TP13.1 v2(13,28)
NetR13_1: R13.1 R14.2 TP19.1 U3.6 | length 5.5
  Top Layer w0.5: R14.2 25.5,52 ; U3.6 25.46,51.96 25.5,52 ; R13.1 25.5,52
  Bottom Layer w0.5: TP19.1 v2(24,52)
NetR19_1: R19.1 R20.2 TP22.1 U3.9 | length 12.8
  Top Layer w0.5: v2(21.15,48.625) 21.95,48.625 22.4,48.175 R19.1 R20.2@22.4,45.275 ; R20.2@22.4,45.25 R20.2@22.4,45.275 ; R20.2@22.869,45.003 R20.2@22.869,45.119 ; U3.9 25.46,46.04 25,46.5 23.65,46.5 22.875,45.725 22.85,45.725 R20.2@22.4,45.275
  Bottom Layer w0.5: TP22.1 20.587,48.587 21.112,48.587 v2(21.15,48.625)
Reset: C9.1 Q3.S Q4.D R17.2 TP21.1 U3.8 | length 46.6
  Top Layer w0.5: U3.8 24.24,44.225 U3.8@24.24,43.8 ; v2(25.25,42) 26.4,42 26.4,42.275 R17.2@25.95,42.725 ; Q3.S 37.65,45.975 38.1,45.975 38.103,45.972 v2(39.168,45.972) ; Q4.D 44.35,41 45.8,42.45 44.57,43.68 v2(44.522,43.68)
  Bottom Layer w0.5: v2(24.25,45.25) 23,44 ; v2(25.25,42) 25.212,42.038 24.962,42.038 23,44 ; v2@44.522,43.718 41.422,43.718 v2(39.168,45.972) TP21.1 25,50 22,47 22,45.25 22,45 23,44
SC_close: R21.2 R22.1 TP23.1 U3.14 | length 45.6
  Top Layer w0.5: R22.1 7.5,19.5 v3(8.75,20.75) ; R21.2 31.4,42.275 R21.2@31.76,42.635 ; U3.14 31.76,44.225 R21.2@31.76,42.635 ; v2(33,46) 33,43.875 R21.2@31.76,42.635
  Bottom Layer w0.5: v3(8.75,20.75) 11.788,23.788 26.878,38.878 27.122,38.878 33,44.757 v2(33,46)
SC_in: J1.2 TP5.1 X1.4 | length 24.9
  Top Layer w1: X1.4 13.43,12.18 v3(13.5,12.25)
  Bottom Layer w1: v3(13.5,12.25) 15.75,14.5 15.75,18.29 18.54,21.08 23,21.08 25.92,21.08 26.975,20.025 J1.2
SC_out: J1.5 TP6.1 X1.5 | length 24.6
  Top Layer w1: X1.5 12.36,9.64 14.5,7.5 21.25,7.5 26.975,13.225 J1.5
  Bottom Layer w1: TP6.1 26.75,12.021 26.975,12.246 J1.5 J1.5@26.852,14.892
SCS_ref_lvl: R7.2 R8.2 TP9.1 U2.6 U2.8 | length 17.6
  Top Layer w0.5: R7.2 10.05,40.05 10.05,39.575 10.981,38.644 ; U2.8 13.19,34.485 11.275,36.4 v2(11,36.4) 10.6,36.8 10.6,38.263 10.893,38.556 13.356,38.556 14.41,37.503 14.41,36.775 U2.6
  Bottom Layer w0.5: TP9.1 10,35.346 11,36.346 v2(11,36.4)
pads on no net: J1. U3.2 U3.4 U3.5 U3.10 U3.11 U3.13 X1.3 X1.8 X1.9 X1.10

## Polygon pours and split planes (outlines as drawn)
GND on Top Layer "GND_L01_P010" (solid, pour order 10): 0,10 0,50 cw(c5,50) 5,55 48,55 cw(c48,50) 53,50 53,10 cw(c48,10) 48,5 5,5 cw(c5,10)
LV+_in on Top Layer "LV+_IN_L01_P003" (solid, pour order 3): 28.167,17.333 31,14.5 41.75,14.5 41.75,17.25 41,18 36.5,18 35,19.5 35,21.529 34.675,21.854 33.625,21.854 33,21.229 33,18.5 28.75,18.5
NetD4_A on Top Layer "NETD4_A_L01_P002" (solid, pour order 2): 40.63,21.77 41.416,21.191 41.416,20.036 40.63,19.25 36.87,19.25 36.254,19.867 36.254,21.403 36.484,21.77
GND on Bottom Layer "GND_L02_P011" (solid, pour order 11): 0,10 0,50 cw(c5,50) 5,55 48,55 cw(c48,50) 53,50 53,10 cw(c48,10) 48,5 5,5 cw(c5,10)

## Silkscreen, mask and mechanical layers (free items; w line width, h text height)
Bottom Overlay:
  drawing of 32 lines, arcs and shapes, not listed
  text "BSPD" at 38.236,26.5 h15
  text "David Redondo & Guillem Ropero - 2024" at 40.497,23.819 h3
Mechanical 1:
  the board outline again, w0.5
